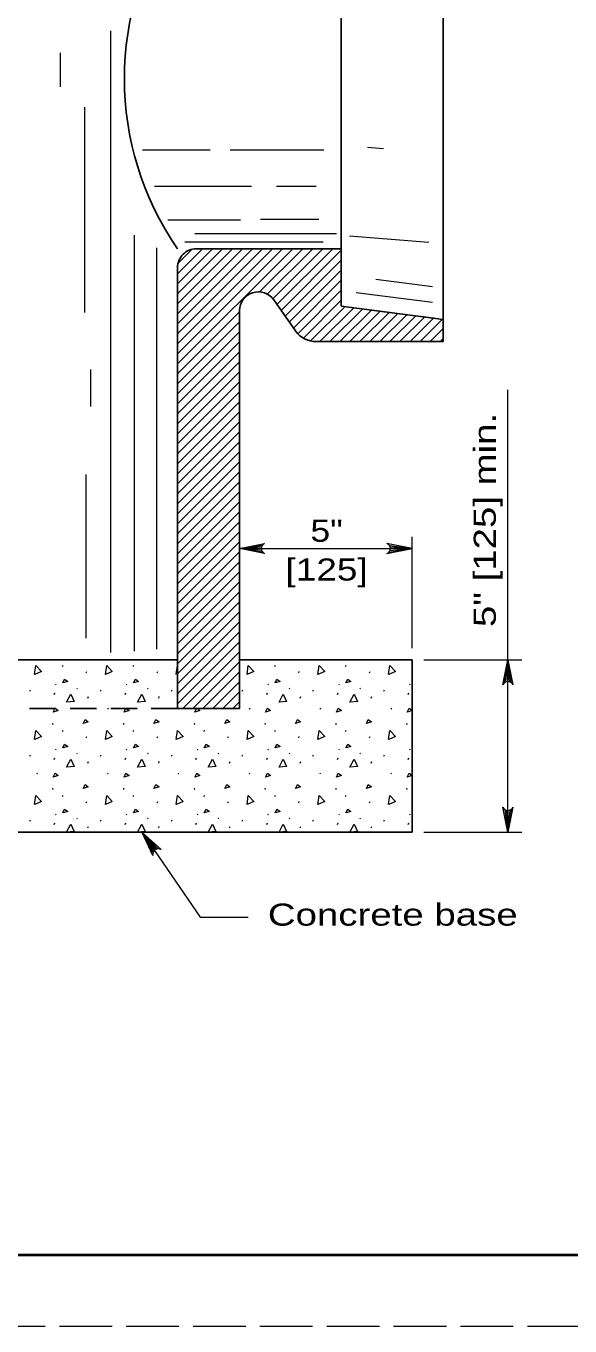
# Model space of a CAD drawing. Extents: x 1302.9 to 1336.9, y 688.5 to 710.5.
# Drawn here: x 1320.58 to 1324.42, y 688.5 to 697.69 of the extents above; entities that cross this region are included whole.
import ezdxf
from ezdxf.enums import TextEntityAlignment as Align

# ---------------------------------------------------------------- set-up
doc = ezdxf.new("R2010")
doc.units = 0
doc.header["$LTSCALE"] = 0.062
doc.linetypes.add('LONG_DASHED', pattern=[7.5, 6, -1.5])
doc.linetypes.add('MEDIUM_DASHED', pattern=[4.5, 3, -1.5])
doc.layers.add('1', color=7, linetype='Continuous', lineweight=13)

msp = doc.modelspace()

# ---------------------------------------------------------------- linework, layer by layer
at = {"layer": '1', "lineweight": 25}
for p, q in [((1323.52108, 699.01758), (1323.52108, 695.61325)), ((1322.80267, 695.70692), (1322.80267, 698.51792)), ((1321.77975, 696.11292), (1322.80267, 696.11292)), ((1322.47875, 695.53342), (1322.32575, 695.75183)), ((1317.24267, 693.20833), (1321.64692, 693.20833))]:
    msp.add_line(p, q, dxfattribs=at)
at = {"layer": '1'}
for p, q in [((1321.17358, 697.65342), (1321.17358, 693.26017)), ((1320.81933, 697.49858), (1320.81933, 697.25742)), ((1320.99033, 697.11442), (1320.99033, 695.6625)), ((1322.9885, 696.83025), (1323.1015, 696.8205)), ((1321.40067, 696.81158), (1321.87667, 696.81158)), ((1322.01942, 696.81158), (1322.67992, 696.81158)), ((1321.48392, 696.55542), (1322.16817, 696.55542)), ((1322.34667, 696.55542), (1322.62633, 696.55542)), ((1321.57917, 696.31717), (1322.09083, 696.31717)), ((1322.23367, 696.32308), (1322.64417, 696.32308)), ((1321.34117, 696.20892), (1321.34117, 693.26933)), ((1321.76958, 696.22175), (1322.76908, 696.22175)), ((1322.86175, 696.20375), (1323.421, 696.15958)), ((1321.49992, 693.28483), (1321.49992, 696.11992)), ((1321.64692, 695.93625), (1321.82358, 696.11292)), ((1321.64692, 695.86567), (1321.89425, 696.11292)), ((1321.64692, 695.79492), (1321.965, 696.11292)), ((1321.64692, 695.72433), (1322.03558, 696.11292)), ((1321.64692, 695.65358), (1322.10633, 696.11292)), ((1321.64692, 695.583), (1322.17692, 696.11292)), ((1321.64692, 695.51225), (1322.24767, 696.11292)), ((1321.64692, 695.44158), (1322.31842, 696.11292)), ((1321.64692, 695.37092), (1322.389, 696.11292)), ((1321.64692, 695.30025), (1322.45975, 696.11292)), ((1321.651, 696.01108), (1321.74883, 696.10883)), ((1321.69817, 696.16225), (1322.67392, 696.16225)), ((1322.22533, 695.80783), (1322.53033, 696.11292)), ((1322.28008, 695.792), (1322.60108, 696.11292)), ((1322.31892, 695.76008), (1322.67175, 696.11292)), ((1322.34858, 695.71917), (1322.74242, 696.11292)), ((1322.37775, 695.67758), (1322.80267, 696.1025)), ((1322.40683, 695.636), (1322.80267, 696.03183)), ((1322.436, 695.5945), (1322.80267, 695.96117)), ((1323.04742, 695.89742), (1323.4465, 695.84533)), ((1322.46508, 695.55292), (1322.80267, 695.8905)), ((1322.496, 695.51308), (1322.80267, 695.81983)), ((1322.9075, 695.80483), (1323.44625, 695.73458)), ((1322.53533, 695.48192), (1322.80267, 695.74917)), ((1321.64692, 695.22958), (1322.08425, 695.66683)), ((1322.58608, 695.462), (1322.82783, 695.70367)), ((1322.65192, 695.45708), (1322.89033, 695.6955)), ((1322.7225, 695.45708), (1322.95283, 695.68733)), ((1322.79325, 695.45708), (1323.01542, 695.67917)), ((1322.85417, 695.70292), (1323.14858, 695.6645)), ((1322.86392, 695.45708), (1323.07783, 695.671)), ((1322.93458, 695.45708), (1323.14042, 695.66283)), ((1323.00533, 695.45708), (1323.203, 695.65467)), ((1323.07592, 695.45708), (1323.26542, 695.6465)), ((1323.14667, 695.45708), (1323.328, 695.63833)), ((1323.21642, 695.65558), (1323.45542, 695.6245)), ((1323.21725, 695.45708), (1323.3905, 695.63025)), ((1323.288, 695.45708), (1323.453, 695.62217)), ((1321.64692, 695.15892), (1322.08425, 695.59617)), ((1323.35867, 695.45708), (1323.51558, 695.614)), ((1323.42933, 695.45708), (1323.52108, 695.54875)), ((1321.64692, 695.08825), (1322.08425, 695.5255)), ((1321.64692, 695.01758), (1322.08425, 695.45483)), ((1323.5, 695.45708), (1323.52108, 695.47817)), ((1321.64692, 694.94692), (1322.08425, 695.38417)), ((1321.03583, 694.9995), (1321.03583, 695.25892)), ((1321.64692, 694.87625), (1322.08425, 695.3135)), ((1321.64692, 694.80558), (1322.08425, 695.24283)), ((1321.64692, 694.73492), (1322.08425, 695.17217)), ((1321.64692, 694.66425), (1322.08425, 695.1015)), ((1323.97933, 691.99092), (1323.97933, 695.116)), ((1321.64692, 694.59358), (1322.08425, 695.03083)), ((1321.64692, 694.52292), (1322.08425, 694.96017)), ((1321.64692, 694.45225), (1322.08425, 694.8895)), ((1321.64692, 694.38158), (1322.08425, 694.81883)), ((1321.64692, 694.31092), (1322.08425, 694.74817)), ((1321.64692, 694.24017), (1322.08425, 694.67742)), ((1320.99892, 694.51717), (1320.99892, 693.36158)), ((1321.64692, 694.16958), (1322.08425, 694.60683)), ((1321.64692, 694.09883), (1322.08425, 694.53608)), ((1321.64692, 694.02825), (1322.08425, 694.4655)), ((1321.64692, 693.9575), (1322.08425, 694.39475)), ((1321.64692, 693.88692), (1322.08425, 694.32417)), ((1321.64692, 693.81617), (1322.08425, 694.25342)), ((1321.64692, 693.74558), (1322.08425, 694.18283)), ((1321.64692, 693.67483), (1322.08425, 694.11208)), ((1323.30242, 693.29167), (1323.30242, 694.07775)), ((1321.64692, 693.60425), (1322.08425, 694.0415)), ((1321.64692, 693.5335), (1322.08425, 693.97075)), ((1322.2445, 694.01692), (1322.08425, 693.9945)), ((1322.23908, 694.00583), (1322.08425, 693.9945)), ((1322.08425, 693.9945), (1323.30242, 693.9945)), ((1322.23742, 693.9945), (1322.08425, 693.9945)), ((1322.24025, 693.98008), (1322.08425, 693.9945)), ((1322.24633, 693.96967), (1322.08425, 693.9945)), ((1323.14025, 693.96967), (1323.30242, 693.9945)), ((1323.14217, 694.01692), (1323.30242, 693.9945)), ((1323.14642, 693.98008), (1323.30242, 693.9945)), ((1323.14758, 694.00583), (1323.30242, 693.9945)), ((1323.14925, 693.9945), (1323.30242, 693.9945)), ((1321.64692, 693.46292), (1322.08425, 693.90008)), ((1321.64692, 693.39217), (1322.08425, 693.82942)), ((1321.64692, 693.3215), (1322.08425, 693.75875)), ((1321.64692, 693.25083), (1322.08425, 693.68808)), ((1321.64692, 693.18017), (1322.08425, 693.61742)), ((1321.64692, 693.1095), (1322.08425, 693.54675)), ((1321.64692, 693.03883), (1322.08425, 693.47608)), ((1321.64692, 692.96817), (1322.08425, 693.40542)), ((1321.64692, 692.89742), (1322.08425, 693.33467)), ((1321.68492, 692.86483), (1322.08425, 693.26408)), ((1320.83425, 693.16158), (1320.83867, 693.17158)), ((1321.334, 693.16158), (1321.33842, 693.17158)), ((1321.75567, 692.86483), (1322.08425, 693.19333)), ((1322.3335, 693.16158), (1322.33792, 693.17158)), ((1322.83333, 693.16158), (1322.83775, 693.17158)), ((1323.38575, 693.20833), (1324.07725, 693.20833)), ((1323.95458, 693.04683), (1323.97933, 693.209)), ((1323.96492, 693.053), (1323.97933, 693.209)), ((1323.97933, 693.05583), (1323.97933, 693.209)), ((1323.99067, 693.05417), (1323.97933, 693.209)), ((1324.00175, 693.04875), (1323.97933, 693.209)), ((1321.00283, 693.11608), (1321.00733, 693.12608)), ((1321.50258, 693.11608), (1321.50708, 693.12608)), ((1321.647, 693.10892), (1321.63858, 693.105)), ((1321.82625, 692.86483), (1322.08425, 693.12275)), ((1321.897, 692.86483), (1322.08425, 693.052)), ((1322.50217, 693.11608), (1322.50658, 693.12608)), ((1323.00192, 693.11608), (1323.00642, 693.12608)), ((1320.60408, 692.98742), (1320.6085, 692.99742)), ((1320.77717, 692.96425), (1320.78158, 692.97425)), ((1320.7855, 693.03733), (1320.79, 693.03075)), ((1320.935, 693.00917), (1320.93942, 693.0025)), ((1321.10383, 692.98742), (1321.10825, 692.99742)), ((1321.27692, 692.96425), (1321.28133, 692.97425)), ((1321.28525, 693.03733), (1321.28975, 693.03075)), ((1321.43483, 693.00917), (1321.43925, 693.0025)), ((1321.60367, 692.98742), (1321.60808, 692.99742)), ((1321.96767, 692.86483), (1322.08425, 692.98142)), ((1322.10342, 692.98742), (1322.10783, 692.99742)), ((1322.2765, 692.96425), (1322.28092, 692.97425)), ((1322.28483, 693.03733), (1322.28933, 693.03075)), ((1322.43433, 693.00917), (1322.43875, 693.0025)), ((1322.60317, 692.98742), (1322.60758, 692.99742)), ((1322.77625, 692.96425), (1322.78067, 692.97425)), ((1322.78458, 693.03733), (1322.78908, 693.03075)), ((1322.93408, 693.00917), (1322.9385, 693.0025)), ((1323.10292, 692.98742), (1323.10733, 692.99742)), ((1323.276, 692.96425), (1323.28042, 692.97425)), ((1323.28433, 693.03733), (1323.28883, 693.03075)), ((1320.65292, 692.86775), (1320.65733, 692.86108)), ((1321.014, 692.93875), (1321.01842, 692.94867)), ((1321.15267, 692.86775), (1321.15708, 692.86108)), ((1321.51375, 692.93875), (1321.51817, 692.94867)), ((1322.03833, 692.86483), (1322.08425, 692.91067)), ((1322.15217, 692.86775), (1322.15658, 692.86108)), ((1322.51325, 692.93875), (1322.51767, 692.94867)), ((1322.652, 692.86775), (1322.65642, 692.86108)), ((1323.01308, 692.93875), (1323.0175, 692.94867)), ((1323.15175, 692.86775), (1323.15617, 692.86108)), ((1321.76892, 692.83892), (1321.77883, 692.85958)), ((1323.30242, 692.84958), (1323.26817, 692.83892)), ((1320.765, 692.76125), (1320.76617, 692.75125)), ((1320.83425, 692.70242), (1320.83867, 692.71242)), ((1321.26483, 692.76125), (1321.26592, 692.75125)), ((1321.334, 692.70242), (1321.33842, 692.71242)), ((1321.76458, 692.76125), (1321.76575, 692.75125)), ((1321.83375, 692.70242), (1321.83817, 692.71242)), ((1322.26433, 692.76125), (1322.2655, 692.75125)), ((1322.3335, 692.70242), (1322.33792, 692.71242)), ((1322.76408, 692.76125), (1322.76525, 692.75125)), ((1322.83333, 692.70242), (1322.83775, 692.71242)), ((1323.26383, 692.76125), (1323.265, 692.75125)), ((1321.00283, 692.65692), (1321.00733, 692.66692)), ((1321.50258, 692.65692), (1321.50708, 692.66692)), ((1322.00233, 692.65692), (1322.00683, 692.66692)), ((1322.50217, 692.65692), (1322.50658, 692.66692)), ((1323.00192, 692.65692), (1323.00642, 692.66692)), ((1320.60408, 692.52825), (1320.6085, 692.53825)), ((1320.77717, 692.50508), (1320.78158, 692.51508)), ((1320.7855, 692.57825), (1320.79, 692.57158)), ((1320.935, 692.55), (1320.93942, 692.54333)), ((1321.10383, 692.52825), (1321.10825, 692.53825)), ((1321.27692, 692.50508), (1321.28133, 692.51508)), ((1321.28525, 692.57825), (1321.28975, 692.57158)), ((1321.43483, 692.55), (1321.43925, 692.54333)), ((1321.60367, 692.52825), (1321.60808, 692.53825)), ((1321.77675, 692.50508), (1321.78117, 692.51508)), ((1321.78508, 692.57825), (1321.78958, 692.57158)), ((1321.93458, 692.55), (1321.939, 692.54333)), ((1322.10342, 692.52825), (1322.10783, 692.53825)), ((1322.2765, 692.50508), (1322.28092, 692.51508)), ((1322.28483, 692.57825), (1322.28933, 692.57158)), ((1322.43433, 692.55), (1322.43875, 692.54333)), ((1322.60317, 692.52825), (1322.60758, 692.53825)), ((1322.77625, 692.50508), (1322.78067, 692.51508)), ((1322.78458, 692.57825), (1322.78908, 692.57158)), ((1322.93408, 692.55), (1322.9385, 692.54333)), ((1323.10292, 692.52825), (1323.10733, 692.53825)), ((1323.276, 692.50508), (1323.28042, 692.51508)), ((1323.28433, 692.57825), (1323.28883, 692.57158)), ((1320.65292, 692.40858), (1320.65733, 692.40192)), ((1321.014, 692.47958), (1321.01842, 692.4895)), ((1321.15267, 692.40858), (1321.15708, 692.40192)), ((1321.51375, 692.47958), (1321.51817, 692.4895)), ((1321.65242, 692.40858), (1321.65683, 692.40192)), ((1322.0135, 692.47958), (1322.01792, 692.4895)), ((1322.15217, 692.40858), (1322.15658, 692.40192)), ((1322.51325, 692.47958), (1322.51767, 692.4895)), ((1322.652, 692.40858), (1322.65642, 692.40192)), ((1323.01308, 692.47958), (1323.0175, 692.4895)), ((1323.15175, 692.40858), (1323.15617, 692.40192)), ((1323.30242, 692.39042), (1323.26817, 692.37975)), ((1320.765, 692.30217), (1320.76617, 692.29217)), ((1320.83425, 692.24325), (1320.83867, 692.25325)), ((1321.26483, 692.30217), (1321.26592, 692.29217)), ((1321.334, 692.24325), (1321.33842, 692.25325)), ((1321.76458, 692.30217), (1321.76575, 692.29217)), ((1321.83375, 692.24325), (1321.83817, 692.25325)), ((1322.26433, 692.30217), (1322.2655, 692.29217)), ((1322.3335, 692.24325), (1322.33792, 692.25325)), ((1322.76408, 692.30217), (1322.76525, 692.29217)), ((1322.83333, 692.24325), (1322.83775, 692.25325)), ((1323.26383, 692.30217), (1323.265, 692.29217)), ((1321.00283, 692.19775), (1321.00733, 692.20775)), ((1321.50258, 692.19775), (1321.50708, 692.20775)), ((1322.00233, 692.19775), (1322.00683, 692.20775)), ((1322.50217, 692.19775), (1322.50658, 692.20775)), ((1323.00192, 692.19775), (1323.00642, 692.20775)), ((1323.95692, 692.15117), (1323.97933, 691.99092)), ((1323.968, 692.14575), (1323.97933, 691.99092)), ((1324.00417, 692.15308), (1323.97933, 691.99092)), ((1323.99375, 692.14692), (1323.97933, 691.99092)), ((1323.97933, 692.14408), (1323.97933, 691.99092)), ((1320.60408, 692.06908), (1320.6085, 692.07908)), ((1320.77717, 692.04592), (1320.78158, 692.05592)), ((1320.7855, 692.11908), (1320.79, 692.11242)), ((1320.935, 692.09083), (1320.93942, 692.08417)), ((1321.10383, 692.06908), (1321.10825, 692.07908)), ((1321.27692, 692.04592), (1321.28133, 692.05592)), ((1321.28525, 692.11908), (1321.28975, 692.11242)), ((1321.43483, 692.09083), (1321.43925, 692.08417)), ((1321.60367, 692.06908), (1321.60808, 692.07908)), ((1321.77675, 692.04592), (1321.78117, 692.05592)), ((1321.78508, 692.11908), (1321.78958, 692.11242)), ((1321.93458, 692.09083), (1321.939, 692.08417)), ((1322.10342, 692.06908), (1322.10783, 692.07908)), ((1322.2765, 692.04592), (1322.28092, 692.05592)), ((1322.28483, 692.11908), (1322.28933, 692.11242)), ((1322.43433, 692.09083), (1322.43875, 692.08417)), ((1322.60317, 692.06908), (1322.60758, 692.07908)), ((1322.77625, 692.04592), (1322.78067, 692.05592)), ((1322.78458, 692.11908), (1322.78908, 692.11242)), ((1322.93408, 692.09083), (1322.9385, 692.08417)), ((1323.10292, 692.06908), (1323.10733, 692.07908)), ((1323.276, 692.04592), (1323.28042, 692.05592)), ((1323.28433, 692.11908), (1323.28883, 692.11242)), ((1321.014, 692.02042), (1321.01842, 692.03033)), ((1321.48758, 691.86567), (1321.39733, 691.98942)), ((1321.47767, 691.85483), (1321.39733, 691.98942)), ((1321.47283, 691.84375), (1321.39733, 691.98942)), ((1321.49775, 691.871), (1321.39733, 691.98942)), ((1321.50992, 691.87317), (1321.39733, 691.98942)), ((1321.51375, 692.02042), (1321.51817, 692.03033)), ((1322.0135, 692.02042), (1322.01792, 692.03033)), ((1322.51325, 692.02042), (1322.51767, 692.03033)), ((1323.01308, 692.02042), (1323.0175, 692.03033)), ((1323.38575, 691.99033), (1324.07725, 691.99033))]:
    msp.add_line(p, q, dxfattribs=at)
at = {"layer": '1', "linetype": 'MEDIUM_DASHED', "lineweight": 25}
msp.add_line((1321.64692, 692.86483), (1317.24267, 692.86483), dxfattribs=at)
at = {"layer": '1', "linetype": 'LONG_DASHED'}
msp.add_lwpolyline([(1302.8765, 688.50158), (1336.8765, 688.50158), (1336.8765, 710.50158), (1302.8765, 710.50158)], close=True, dxfattribs=at)
at = {"layer": '1', "lineweight": 25}
for points in [[(1336.3765, 689.00158), (1304.8765, 689.00158), (1304.8765, 710.00158)], [(1322.08425, 695.67567), (1322.08425, 692.86483), (1321.64692, 692.86483), (1321.64692, 695.98017)], [(1322.80267, 695.70692), (1323.52108, 695.61325), (1323.52108, 695.45708), (1322.62542, 695.45708)], [(1323.30242, 691.99033), (1315.58733, 691.99033), (1315.58733, 693.20833), (1316.80542, 693.20833)], [(1322.08425, 693.20833), (1323.30242, 693.20833), (1323.30242, 691.99033)]]:
    msp.add_lwpolyline(points, dxfattribs=at)
at = {"layer": '1', "lineweight": 40}
msp.add_lwpolyline([(1304.8765, 710.00158), (1336.3765, 710.00158), (1336.3765, 689.00158), (1304.8765, 689.00158)], close=True, dxfattribs=at)
msp.add_lwpolyline([(1304.8765, 710.00158), (1336.3765, 710.00158), (1336.3765, 689.00158), (1304.8765, 689.00158)], close=True, dxfattribs=at)
at = {"layer": '1'}
for points in [[(1322.26125, 693.95908), (1322.08425, 693.9945), (1322.26125, 694.02992)], [(1323.12542, 693.95908), (1323.30242, 693.9945), (1323.12542, 694.02992)], [(1320.63808, 693.10458), (1320.64692, 693.16808), (1320.68667, 693.127), (1320.63908, 693.105)], [(1321.13783, 693.10458), (1321.14667, 693.16808), (1321.18642, 693.127), (1321.13883, 693.105)], [(1321.63758, 693.10458), (1321.64642, 693.16808), (1321.647, 693.1675)], [(1322.13742, 693.10458), (1322.14625, 693.16808), (1322.18592, 693.127), (1322.13842, 693.105)], [(1322.63717, 693.10458), (1322.646, 693.16808), (1322.68567, 693.127), (1322.63817, 693.105)], [(1323.13692, 693.10458), (1323.14575, 693.16808), (1323.1855, 693.127), (1323.13792, 693.105)], [(1323.94392, 693.032), (1323.97933, 693.209), (1324.01475, 693.032)], [(1320.86417, 692.90875), (1320.89417, 692.96533), (1320.91742, 692.91317), (1320.86533, 692.90875)], [(1321.36392, 692.90875), (1321.39392, 692.96533), (1321.41725, 692.91317), (1321.36508, 692.90875)], [(1322.36342, 692.90875), (1322.39342, 692.96533), (1322.41675, 692.91317), (1322.36458, 692.90875)], [(1322.86317, 692.90875), (1322.89317, 692.96533), (1322.9165, 692.91317), (1322.86433, 692.90875)], [(1323.26817, 692.83892), (1323.2815, 692.86667), (1323.30242, 692.851)], [(1321.79167, 692.85958), (1321.80442, 692.85), (1321.76892, 692.83892)], [(1320.63808, 692.64542), (1320.64692, 692.70892), (1320.68667, 692.66783), (1320.63908, 692.64583)], [(1321.13783, 692.64542), (1321.14667, 692.70892), (1321.18642, 692.66783), (1321.13883, 692.64583)], [(1321.63758, 692.64542), (1321.64642, 692.70892), (1321.68617, 692.66783), (1321.63858, 692.64583)], [(1322.13742, 692.64542), (1322.14625, 692.70892), (1322.18592, 692.66783), (1322.13842, 692.64583)], [(1322.63717, 692.64542), (1322.646, 692.70892), (1322.68567, 692.66783), (1322.63817, 692.64583)], [(1323.13692, 692.64542), (1323.14575, 692.70892), (1323.1855, 692.66783), (1323.13792, 692.64583)], [(1320.86417, 692.44967), (1320.89417, 692.50617), (1320.91742, 692.454), (1320.86533, 692.44967)], [(1321.36392, 692.44967), (1321.39392, 692.50617), (1321.41725, 692.454), (1321.36508, 692.44967)], [(1321.86367, 692.44967), (1321.89367, 692.50617), (1321.917, 692.454), (1321.86483, 692.44967)], [(1322.36342, 692.44967), (1322.39342, 692.50617), (1322.41675, 692.454), (1322.36458, 692.44967)], [(1322.86317, 692.44967), (1322.89317, 692.50617), (1322.9165, 692.454), (1322.86433, 692.44967)], [(1323.26817, 692.37975), (1323.2815, 692.4075), (1323.30242, 692.39183)], [(1320.63808, 692.18625), (1320.64692, 692.24975), (1320.68667, 692.20867), (1320.63908, 692.18667)], [(1321.13783, 692.18625), (1321.14667, 692.24975), (1321.18642, 692.20867), (1321.13883, 692.18667)], [(1321.63758, 692.18625), (1321.64642, 692.24975), (1321.68617, 692.20867), (1321.63858, 692.18667)], [(1322.13742, 692.18625), (1322.14625, 692.24975), (1322.18592, 692.20867), (1322.13842, 692.18667)], [(1322.63717, 692.18625), (1322.646, 692.24975), (1322.68567, 692.20867), (1322.63817, 692.18667)], [(1323.13692, 692.18625), (1323.14575, 692.24975), (1323.1855, 692.20867), (1323.13792, 692.18667)], [(1324.01475, 692.16792), (1323.97933, 691.99092), (1323.94392, 692.16792)], [(1320.86417, 691.9905), (1320.89417, 692.047), (1320.91742, 691.99492), (1320.86533, 691.9905)], [(1321.36392, 691.9905), (1321.39392, 692.047), (1321.41725, 691.99492), (1321.36508, 691.9905)], [(1321.86367, 691.9905), (1321.89367, 692.047), (1321.917, 691.99492), (1321.86483, 691.9905)], [(1322.36342, 691.9905), (1322.39342, 692.047), (1322.41675, 691.99492), (1322.36458, 691.9905)], [(1322.86317, 691.9905), (1322.89317, 692.047), (1322.9165, 691.99492), (1322.86433, 691.9905)], [(1321.47308, 691.8255), (1321.39733, 691.98942), (1321.53025, 691.86725)], [(1321.39733, 691.98942), (1321.80592, 691.39125), (1322.14475, 691.39125)]]:
    msp.add_lwpolyline(points, dxfattribs=at)
for points in [[(1320.83642, 693.04508), (1320.84975, 693.07283), (1320.872, 693.05617)], [(1321.33617, 693.04508), (1321.3495, 693.07283), (1321.37175, 693.05617)], [(1322.33567, 693.04508), (1322.349, 693.07283), (1322.37125, 693.05617)], [(1322.8355, 693.04508), (1322.84883, 693.07283), (1322.871, 693.05617)], [(1320.76933, 692.83892), (1320.78267, 692.86667), (1320.80492, 692.85)], [(1321.26908, 692.83892), (1321.28242, 692.86667), (1321.30467, 692.85)], [(1322.26867, 692.83892), (1322.282, 692.86667), (1322.30425, 692.85)], [(1322.76842, 692.83892), (1322.78175, 692.86667), (1322.804, 692.85)], [(1320.98092, 692.7595), (1320.99425, 692.78733), (1321.01642, 692.77067)], [(1321.48067, 692.7595), (1321.494, 692.78733), (1321.51617, 692.77067)], [(1321.98042, 692.7595), (1321.99375, 692.78733), (1322.01592, 692.77067)], [(1322.48025, 692.7595), (1322.49358, 692.78733), (1322.51567, 692.77067)], [(1322.98, 692.7595), (1322.99333, 692.78733), (1323.0155, 692.77067)], [(1320.83642, 692.586), (1320.84975, 692.61367), (1320.872, 692.597)], [(1321.33617, 692.586), (1321.3495, 692.61367), (1321.37175, 692.597)], [(1321.83592, 692.586), (1321.84925, 692.61367), (1321.8715, 692.597)], [(1322.33567, 692.586), (1322.349, 692.61367), (1322.37125, 692.597)], [(1322.8355, 692.586), (1322.84883, 692.61367), (1322.871, 692.597)], [(1320.76933, 692.37975), (1320.78267, 692.4075), (1320.80492, 692.39083)], [(1321.26908, 692.37975), (1321.28242, 692.4075), (1321.30467, 692.39083)], [(1321.76892, 692.37975), (1321.78225, 692.4075), (1321.80442, 692.39083)], [(1322.26867, 692.37975), (1322.282, 692.4075), (1322.30425, 692.39083)], [(1322.76842, 692.37975), (1322.78175, 692.4075), (1322.804, 692.39083)], [(1320.98092, 692.3005), (1320.99425, 692.32817), (1321.01642, 692.3115)], [(1321.48067, 692.3005), (1321.494, 692.32817), (1321.51617, 692.3115)], [(1321.98042, 692.3005), (1321.99375, 692.32817), (1322.01592, 692.3115)], [(1322.48025, 692.3005), (1322.49358, 692.32817), (1322.51567, 692.3115)], [(1322.98, 692.3005), (1322.99333, 692.32817), (1323.0155, 692.3115)], [(1320.83642, 692.12683), (1320.84975, 692.15458), (1320.872, 692.13792)], [(1321.33617, 692.12683), (1321.3495, 692.15458), (1321.37175, 692.13792)], [(1321.83592, 692.12683), (1321.84925, 692.15458), (1321.8715, 692.13792)], [(1322.33567, 692.12683), (1322.349, 692.15458), (1322.37125, 692.13792)], [(1322.8355, 692.12683), (1322.84883, 692.15458), (1322.871, 692.13792)]]:
    msp.add_lwpolyline(points, close=True, dxfattribs=at)
for centre, start, end in [((1322.27554, 693.99452), 112.08782, 247.91395), ((1323.11113, 693.99452), 292.08605, 67.91218), ((1323.97939, 693.01768), 22.08782, 157.91395), ((1323.97931, 692.18222), 202.08782, 337.91395), ((1321.5101, 691.83485), 58.18971, 194.01584)]:
    msp.add_arc(centre, 0.0382, start, end, dxfattribs=at)
at = {"layer": '1', "lineweight": 25}
for centre, major_axis, start_param, end_param in [((1323.38877, 697.31541), (-2.11665, 0), 5.6789146, 6.8874561), ((1321.7797, 695.9802), (0.13275, 0), 1.5707963, 3.1415927), ((1322.21701, 695.67568), (0.13277, 0), 0.6106232, 3.1415927), ((1322.62543, 695.63613), (0.17909, 0), 3.7523998, 4.7122583)]:
    msp.add_ellipse(centre, major_axis=major_axis, ratio=0.999895, start_param=start_param, end_param=end_param, dxfattribs=at)

# ---------------------------------------------------------------- texts
at = {"layer": '1', "width": 1.3}
msp.add_text('5" [125] min.', height=0.156, rotation=90, dxfattribs=at).set_placement((1323.89392, 694.19683), align=Align.CENTER)
at = {"layer": '1'}
for s, width, p in [('5"', 1.2, (1322.69921, 694.04275)), ('[125]', 1.25, (1322.69917, 693.76875))]:
    msp.add_text(s, height=0.156, dxfattribs=dict(at, width=width)).set_placement(p, align=Align.CENTER)
at = {"layer": '1', "width": 1.3}
msp.add_text('Concrete base', height=0.156, dxfattribs=at).set_placement((1322.28442, 691.33033))

doc.saveas('drawing.dxf')
